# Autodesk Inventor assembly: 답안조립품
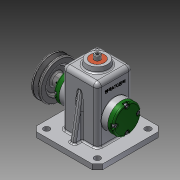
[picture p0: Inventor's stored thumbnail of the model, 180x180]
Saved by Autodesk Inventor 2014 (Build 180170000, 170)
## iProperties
Created: 2016-02
Part Number: 답안조립품
Document SubType Name: Assembly
Designer: Administrator
Author: Administrator
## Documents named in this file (16)
- C:\Users\Administrator\Desktop\460211V1028\답안조립품.iam
- C:\Users\Administrator\Desktop\460211V1028\1-본체.ipt
- C:\Users\Administrator\Desktop\460211V1028\V벨트풀리.ipt
- C:\Users\Administrator\Desktop\460211V1028\고정핀 1.2 x 10.ipt
- C:\Users\Administrator\Desktop\460211V1028\뒤커버.ipt
- C:\Users\Administrator\Desktop\460211V1028\링크.ipt
- C:\Users\Administrator\Desktop\460211V1028\멈춤나사 M3x8.ipt
- C:\Users\Administrator\Desktop\460211V1028\베어링 12 x 32 x 10.ipt
- C:\Users\Administrator\Desktop\460211V1028\볼트 M4 x 12.ipt
- C:\Users\Administrator\Desktop\460211V1028\부시.ipt
- C:\Users\Administrator\Desktop\460211V1028\슬라이드.ipt
- C:\Users\Administrator\Desktop\460211V1028\앞커버.ipt
- C:\Users\Administrator\Desktop\460211V1028\오일실 12 25 7.ipt
- C:\Users\Administrator\Desktop\460211V1028\키 4 x 4 x 10.ipt
- C:\Users\Administrator\Desktop\460211V1028\편심축.ipt
- C:\Users\Administrator\Desktop\460211V1028\핀 5 x 18.ipt
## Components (12 placed, 5 different names)
1. 1-본체:1 — 각도:4, 각도:5
2. V벨트풀리:1 — 플러쉬:2
3. 고정핀 1.2 x 10:1 — 각도:6, 각도:7
4. 핀 5 x 18:1
5. ISO 4762 M4 x 12:1 — 각도:4
6. ISO 4762 M4 x 12:3
7. ISO 4762 M4 x 12:4
8. ISO 4762 M4 x 12:5
9. ISO 4762 M4 x 12:2 — 각도:5
10. ISO 4762 M4 x 12:6
11. ISO 4762 M4 x 12:7
12. ISO 4762 M4 x 12:8
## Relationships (5: Angle 4, Flush 1)
- 각도:4 [Angle]: 1-본체:1 ↔ ISO 4762 M4 x 12:1
- 각도:5 [Angle]: 1-본체:1 ↔ ISO 4762 M4 x 12:2
- 플러쉬:2 [Flush]: V벨트풀리:1
- 각도:6 [Angle]: 고정핀 1.2 x 10:1
- 각도:7 [Angle]: 고정핀 1.2 x 10:1
